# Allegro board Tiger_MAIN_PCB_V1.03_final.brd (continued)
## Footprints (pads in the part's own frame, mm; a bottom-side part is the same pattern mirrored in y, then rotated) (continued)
SMD-BATTERY-2900P-2N
  rect 3x4.2 smd: 1(14.5,0) 2(-14.5,0)
SMD-CN-50P-20N-H
  oval 0.28x1.25 smd: 1(-4.75,2.325) 2(-4.25,2.325) 3(-3.75,2.325) 4(-3.25,2.325) 5(-2.75,2.325) 6(-2.25,2.325) 7(-1.75,2.325) 8(-1.25,2.325) 9(-0.75,2.325) 10(-0.25,2.325) 11(0.25,2.325) 12(0.75,2.325) 13(1.25,2.325) 14(1.75,2.325) 15(2.25,2.325) 16(2.75,2.325) 17(3.25,2.325) 18(3.75,2.325) 19(4.25,2.325) 20(4.75,2.325)
  rect 2x3.4 smd: E1(-6.44,0.4) E2(6.44,0.4)
SMD-CN-100P-2N-V-CB
  rect 0.6x1.5 smd: 1(0.5,2.55) 2(-0.5,2.55)
  rect 1.2x1.8 smd: E1(-1.8,0) E2(1.8,0)
SMD-CN-100P-4N-V-CB
  rect 0.6x1.5 smd: 1(1.5,2.55) 2(0.5,2.55) 3(-0.5,2.55) 4(-1.5,2.55)
  rect 1.2x1.8 smd: E1(-2.8,0) E2(2.8,0)
SMD-CN-100P-6N-H
  rect 0.6x1.55 smd: 1(-2.5,3.875) 2(-1.5,3.875) 3(-0.5,3.875) 4(0.5,3.875) 5(1.5,3.875) 6(2.5,3.875)
  rect 1.2x2 smd: E1(-3.8,0) E2(3.8,0)
SMD-CN-100P-40AN-H
  rect 0.6x1.6 smd: 1(-9.5,-2.9) 2(-8.5,-2.9) 3(-7.5,-2.9) 4(-6.5,-2.9) 5(-5.5,-2.9) 6(-4.5,-2.9) 7(-3.5,-2.9) 8(-2.5,-2.9) 9(-1.5,-2.9) 10(-0.5,-2.9) 11(0.5,-2.9) 12(1.5,-2.9) 13(2.5,-2.9) 14(3.5,-2.9) 15(4.5,-2.9) 16(5.5,-2.9) 17(6.5,-2.9) 18(7.5,-2.9) 19(8.5,-2.9) 20(9.5,-2.9) 21(9.5,2.9) 22(8.5,2.9) 23(7.5,2.9) 24(6.5,2.9) 25(5.5,2.9) 26(4.5,2.9) 27(3.5,2.9) 28(2.5,2.9) 29(1.5,2.9) 30(0.5,2.9) 31(-0.5,2.9) 32(-1.5,2.9) 33(-2.5,2.9) 34(-3.5,2.9) 35(-4.5,2.9) 36(-5.5,2.9) 37(-6.5,2.9) 38(-7.5,2.9) 39(-8.5,2.9) 40(-9.5,2.9)
  rect 1.5x2.3 smd: E1(-11.5,-1.3) E2(11.5,-1.3)
SMD-CN-125P-2WBN
  rect 0.8x1.5 smd: 1(-0.625,2.49) 2(0.625,2.49)
  rect 2x2.5 smd: E1(-3.175,0) E2(3.175,0)
SMD-DDR4-50X820P-260N-AR
  round 1.1 hole 1.1 unplated: (-34.4,0)
  round 1.6 hole 1.6 unplated: (34.4,0)
  rect 0.28x2 smd: 1(33.375,4.1) 2(33.125,-4.1) 3(32.875,4.1) 4(32.625,-4.1) 5(32.375,4.1) 6(32.125,-4.1) 7(31.875,4.1) 8(31.625,-4.1) 9(31.375,4.1) 10(31.125,-4.1) 11(30.875,4.1) 12(30.625,-4.1) 13(30.375,4.1) 14(30.125,-4.1) 15(29.875,4.1) 16(29.625,-4.1) 17(29.375,4.1) 18(29.125,-4.1) 19(28.875,4.1) 20(28.625,-4.1) 21(28.375,4.1) 22(28.125,-4.1) 23(27.875,4.1) 24(27.625,-4.1) 25(27.375,4.1) 26(27.125,-4.1) 27(26.875,4.1) 28(26.625,-4.1) 29(26.375,4.1) 30(26.125,-4.1) 31(25.875,4.1) 32(25.625,-4.1) 33(25.375,4.1) 34(25.125,-4.1) 35(24.875,4.1) 36(24.625,-4.1) 37(24.375,4.1) 38(24.125,-4.1) 39(23.875,4.1) 40(23.625,-4.1) 41(23.375,4.1) 42(23.125,-4.1) 43(22.875,4.1) 44(22.625,-4.1) 45(22.375,4.1) 46(22.125,-4.1) 47(21.875,4.1) 48(21.625,-4.1) 49(21.375,4.1) 50(21.125,-4.1) 51(20.875,4.1) 52(20.625,-4.1) 53(20.375,4.1) 54(20.125,-4.1) 55(19.875,4.1) 56(19.625,-4.1) 57(19.375,4.1) 58(19.125,-4.1) 59(18.875,4.1) 60(18.625,-4.1) 61(18.375,4.1) 62(18.125,-4.1) 63(17.875,4.1) 64(17.625,-4.1) 65(17.375,4.1) 66(17.125,-4.1) 67(16.875,4.1) 68(16.625,-4.1) 69(16.375,4.1) 70(16.125,-4.1) 71(15.875,4.1) 72(15.625,-4.1) 73(15.375,4.1) 74(15.125,-4.1) 75(14.875,4.1) 76(14.625,-4.1) 77(14.375,4.1) 78(14.125,-4.1) 79(13.875,4.1) 80(13.625,-4.1) 81(13.375,4.1) 82(13.125,-4.1) 83(12.875,4.1) 84(12.625,-4.1) 85(12.375,4.1) 86(12.125,-4.1) 87(11.875,4.1) 88(11.625,-4.1) 89(11.375,4.1) 90(11.125,-4.1) 91(10.875,4.1) 92(10.625,-4.1) 93(10.375,4.1) 94(10.125,-4.1) 95(9.875,4.1) 96(9.625,-4.1) 97(9.375,4.1) 98(9.125,-4.1) 99(8.875,4.1) 100(8.625,-4.1) 101(8.375,4.1) 102(8.125,-4.1) 103(7.875,4.1) 104(7.625,-4.1) 105(7.375,4.1) 106(7.125,-4.1) 107(6.875,4.1) 108(6.625,-4.1) 109(6.375,4.1) 110(6.125,-4.1) 111(5.875,4.1) 112(5.625,-4.1) 113(5.375,4.1) 114(5.125,-4.1) 115(4.875,4.1) 116(4.625,-4.1) 117(4.375,4.1) 118(4.125,-4.1) 119(3.875,4.1) 120(3.625,-4.1) 121(3.375,4.1) 122(3.125,-4.1) 123(2.875,4.1) 124(2.625,-4.1) 125(2.375,4.1) 126(2.125,-4.1) 127(1.875,4.1) 128(1.625,-4.1) 129(1.375,4.1) 130(1.125,-4.1) 131(0.875,4.1) 132(0.625,-4.1) 133(0.375,4.1) 134(0.125,-4.1) 135(-0.125,4.1) 136(-0.375,-4.1) 137(-0.625,4.1) 138(-0.875,-4.1) 139(-1.125,4.1) 140(-1.375,-4.1) 141(-1.625,4.1) 142(-1.875,-4.1) 143(-2.125,4.1) 144(-2.375,-4.1) 145(-4.625,4.1) 146(-4.875,-4.1) 147(-5.125,4.1) 148(-5.375,-4.1) 149(-5.625,4.1) 150(-5.875,-4.1) 151(-6.125,4.1) 152(-6.375,-4.1) 153(-6.625,4.1) 154(-6.875,-4.1) 155(-7.125,4.1) 156(-7.375,-4.1) 157(-7.625,4.1) 158(-7.875,-4.1) 159(-8.125,4.1) 160(-8.375,-4.1) 161(-8.625,4.1) 162(-8.875,-4.1) 163(-9.125,4.1) 164(-9.375,-4.1) 165(-9.625,4.1) 166(-9.875,-4.1) 167(-10.125,4.1) 168(-10.375,-4.1) 169(-10.625,4.1) 170(-10.875,-4.1) 171(-11.125,4.1) 172(-11.375,-4.1) 173(-11.625,4.1) 174(-11.875,-4.1) 175(-12.125,4.1) 176(-12.375,-4.1) 177(-12.625,4.1) 178(-12.875,-4.1) 179(-13.125,4.1) 180(-13.375,-4.1) 181(-13.625,4.1) 182(-13.875,-4.1) 183(-14.125,4.1) 184(-14.375,-4.1) 185(-14.625,4.1) 186(-14.875,-4.1) 187(-15.125,4.1) 188(-15.375,-4.1) 189(-15.625,4.1) 190(-15.875,-4.1) 191(-16.125,4.1) 192(-16.375,-4.1) 193(-16.625,4.1) 194(-16.875,-4.1) 195(-17.125,4.1) 196(-17.375,-4.1) 197(-17.625,4.1) 198(-17.875,-4.1) 199(-18.125,4.1) 200(-18.375,-4.1) 201(-18.625,4.1) 202(-18.875,-4.1) 203(-19.125,4.1) 204(-19.375,-4.1) 205(-19.625,4.1) 206(-19.875,-4.1) 207(-20.125,4.1) 208(-20.375,-4.1) 209(-20.625,4.1) 210(-20.875,-4.1) 211(-21.125,4.1) 212(-21.375,-4.1) 213(-21.625,4.1) 214(-21.875,-4.1) 215(-22.125,4.1) 216(-22.375,-4.1) 217(-22.625,4.1) 218(-22.875,-4.1) 219(-23.125,4.1) 220(-23.375,-4.1) 221(-23.625,4.1) 222(-23.875,-4.1) 223(-24.125,4.1) 224(-24.375,-4.1) 225(-24.625,4.1) 226(-24.875,-4.1) 227(-25.125,4.1) 228(-25.375,-4.1) 229(-25.625,4.1) 230(-25.875,-4.1) 231(-26.125,4.1) 232(-26.375,-4.1) 233(-26.625,4.1) 234(-26.875,-4.1) 235(-27.125,4.1) 236(-27.375,-4.1) 237(-27.625,4.1) 238(-27.875,-4.1) 239(-28.125,4.1) 240(-28.375,-4.1) 241(-28.625,4.1) 242(-28.875,-4.1) 243(-29.125,4.1) 244(-29.375,-4.1) 245(-29.625,4.1) 246(-29.875,-4.1) 247(-30.125,4.1) 248(-30.375,-4.1) 249(-30.625,4.1) 250(-30.875,-4.1) 251(-31.125,4.1) 252(-31.375,-4.1) 253(-31.625,4.1) 254(-31.875,-4.1) 255(-32.125,4.1) 256(-32.375,-4.1) 257(-32.625,4.1) 258(-32.875,-4.1) 259(-33.125,4.1) 260(-33.375,-4.1)
  rect 3.6x4.6 smd: E1(-33.8,12) E2(33.8,12)
SMD-M2PCIE-50X750P-75AN
  round 0.254 hole 1.092 unplated: (-10,-1.499)
  round 0.254 hole 1.6 unplated: (10,-1.499)
  rect 0.305x1.575 smd: 1(-9.25,3.763) 2(-9,-3.763) 3(-8.75,3.763) 4(-8.5,-3.763) 5(-8.25,3.763) 6(-8,-3.763) 7(-7.75,3.763) 8(-7.5,-3.763) 9(-7.25,3.763) 10(-7,-3.763) 11(-6.75,3.763) 12(-6.5,-3.763) 13(-6.25,3.763) 14(-6,-3.763) 15(-5.75,3.763) 16(-5.5,-3.763) 17(-5.25,3.763) 18(-5,-3.763) 19(-4.75,3.763) 20(-4.5,-3.763) 21(-4.25,3.763) 22(-4,-3.763) 23(-3.75,3.763) 24(-3.5,-3.763) 25(-3.25,3.763) 26(-3,-3.763) 27(-2.75,3.763) 28(-2.5,-3.763) 29(-2.25,3.763) 30(-2,-3.763) 31(-1.75,3.763) 32(-1.5,-3.763) 33(-1.25,3.763) 34(-1,-3.763) 35(-0.75,3.763) 36(-0.5,-3.763) 37(-0.25,3.763) 38(0,-3.763) 39(0.25,3.763) 40(0.5,-3.763) 41(0.75,3.763) 42(1,-3.763) 43(1.25,3.763) 44(1.5,-3.763) 45(1.75,3.763) 46(2,-3.763) 47(2.25,3.763) 48(2.5,-3.763) 49(2.75,3.763) 50(3,-3.763) 51(3.25,3.763) 52(3.5,-3.763) 53(3.75,3.763) 54(4,-3.763) 55(4.25,3.763) 56(4.5,-3.763) 57(4.75,3.763) 58(5,-3.763) 59(5.25,3.763) 60(5.5,-3.763) 61(5.75,3.763) 62(6,-3.763) 63(6.25,3.763) 64(6.5,-3.763) 65(6.75,3.763) 66(7,-3.763) 67(7.25,3.763) 68(7.5,-3.763) 69(7.75,3.763) 70(8,-3.763) 71(8.25,3.763) 72(8.5,-3.763) 73(8.75,3.763) 74(9,-3.763) 75(9.25,3.763)
  rect 1.219x2.769 smd: E1(-10.39,3.001) E2(10.39,3.001)
SMD-M2PCIE-50X750P-75BN
  round 0.254 hole 1.092 unplated: (-10,-1.499)
  round 0.254 hole 1.6 unplated: (10,-1.499)
  rect 0.305x1.575 smd: 1(-9.25,3.763) 2(-9,-3.763) 3(-8.75,3.763) 4(-8.5,-3.763) 5(-8.25,3.763) 6(-8,-3.763) 7(-7.75,3.763) 8(-7.5,-3.763) 9(-7.25,3.763) 10(-7,-3.763) 11(-6.75,3.763) 12(-6.5,-3.763) 13(-6.25,3.763) 14(-6,-3.763) 15(-5.75,3.763) 16(-5.5,-3.763) 17(-5.25,3.763) 18(-5,-3.763) 19(-4.75,3.763) 20(-4.5,-3.763) 21(-4.25,3.763) 22(-4,-3.763) 23(-3.75,3.763) 24(-3.5,-3.763) 25(-3.25,3.763) 26(-3,-3.763) 27(-2.75,3.763) 28(-2.5,-3.763) 29(-2.25,3.763) 30(-2,-3.763) 31(-1.75,3.763) 32(-1.5,-3.763) 33(-1.25,3.763) 34(-1,-3.763) 35(-0.75,3.763) 36(-0.5,-3.763) 37(-0.25,3.763) 38(0,-3.763) 39(0.25,3.763) 40(0.5,-3.763) 41(0.75,3.763) 42(1,-3.763) 43(1.25,3.763) 44(1.5,-3.763) 45(1.75,3.763) 46(2,-3.763) 47(2.25,3.763) 48(2.5,-3.763) 49(2.75,3.763) 50(3,-3.763) 51(3.25,3.763) 52(3.5,-3.763) 53(3.75,3.763) 54(4,-3.763) 55(4.25,3.763) 56(4.5,-3.763) 57(4.75,3.763) 58(5,-3.763) 67(7.25,3.763) 68(7.5,-3.763) 69(7.75,3.763) 70(8,-3.763) 71(8.25,3.763) 72(8.5,-3.763) 73(8.75,3.763) 74(9,-3.763) 75(9.25,3.763)
  rect 1.219x2.769 smd: E1(-10.39,3.001) E2(10.39,3.001)
SMD-SATA-127P-22AN-L-KX
  round 1.4 hole 1.4 unplated: (-17,-1.35) (17,-1.35)
  oval 1.6x3.3 hole 1x2.6: E1(-18.71,1.05) E2(18.71,1.05)
  rect 0.9x2.6 smd: P1(-1.905,1.05) P2(-0.635,1.05) P3(0.635,1.05) P4(1.905,1.05) P5(3.175,1.05) P6(4.445,1.05) P7(5.715,1.05) P8(6.985,1.05) P9(8.255,1.05) P10(9.525,1.05) P11(10.795,1.05) P12(12.065,1.05) P13(13.335,1.05) P14(14.605,1.05) P15(15.875,1.05) S1(-15.875,1.05) S2(-14.605,1.05) S3(-13.335,1.05) S4(-12.065,1.05) S5(-10.795,1.05) S6(-9.525,1.05) S7(-8.255,1.05)
SMD-SD-250P-9N
  round 1 hole 1 unplated: (-11.45,6.5)
  round 1.5 hole 1.5 unplated: (9.53,6.5)
  rect 0.7x1.9 smd: 1(6.8,9.25) 2(4.3,9.25) 3(1.8,9.25) 4(-0.7,9.25) 5(-3.2,9.25) 6(-5.7,9.25) 7(-8.2,9.25) 8(-9.83,9.25) 9(9.3,9.25) 10(-12.37,9.25) 11(-11.08,9.25)
  rect 1.6x1.6 smd: E1(-14.05,7.55) E2(11.75,7.55) E3(-14.05,-6.65) E4(14.05,-6.65)
SMD-USB-100P-9AN
  rect 0.7x1.65 smd: 1(-3,1) 2(-1,1) 3(1,1) 4(3,1) 5(4,1) 6(2,1) 7(0,1) 8(-2,1) 9(-4,1)
  oval 1.6x3.4 hole 0.6x2.4: E1(-7.9,0) E2(7.9,0)
  rect 1.7x2.3 smd: E3(-7.68,-4.2) E4(7.68,-4.2)
SMY126X63
  rect 1.803x0.991 smd: 1(0,1.245) 2(0,-1.245)
SOD0806N
  rect 0.4x0.35 smd: N(-0.45,0) P(0.45,0)
SOD1713N
  rect 0.8x0.6 smd: N(1.25,0) P(-1.25,0)
SOD2514N
  rect 1.2x0.5 smd: N(-1.15,0) P(1.15,0)
SOD2818N
  rect 2.2x1.4 smd: N(1,0)
  rect 0.9x1.4 smd: P(-1.65,0)
SOD5225N
  rect 2x2 smd: N(-2.095,0) P(2.095,0)
SOD5336N
  rect 2.5x2.3 smd: N(2.15,0) P(-2.15,0)
SOIC127P540-8N
  rect 1.9x0.6 smd: 1(0,0) 2(0,-1.27) 3(0,-2.54) 4(0,-3.81) 5(6.756,-3.81) 6(6.756,-2.54) 7(6.756,-1.27) 8(6.756,0)
SOIC127P600-8N
  rect 1.9x0.6 smd: 1(-2.55,1.905) 2(-2.55,0.635) 3(-2.55,-0.635) 4(-2.55,-1.905) 5(2.55,-1.905) 6(2.55,-0.635) 7(2.55,0.635) 8(2.55,1.905)
SOIC127P605X520-8N
  rect 0.7x0.5 smd: 1(-2.825,1.905) 2(-2.825,0.635) 3(-2.825,-0.635) 4(-2.825,-1.905) 5(2.825,-1.905) 6(2.825,-0.635) 7(2.825,0.635)
  custom 1.12x1.12 smd: 8(0.7,0)
SOIC127P800-8N
  rect 1.8x0.6 smd: 1(-3.6,1.905) 2(-3.6,0.635) 3(-3.6,-0.635) 4(-3.6,-1.905) 5(3.6,-1.905) 6(3.6,-0.635) 7(3.6,0.635) 8(3.6,1.905)
SON50P200X200-8N
  oval 0.6x0.25 smd: 1(-1,0.749) 2(-1,0.249) 3(-1,-0.251) 4(-1,-0.751) 5(1,-0.751) 6(1,-0.251) 7(1,0.249) 8(1,0.749)
  rect 0.9x1.6 smd: E1(0,0)
SON65P330X330-8N
  rect 0.65x0.35 smd: 1(-1.65,0.975) 2(-1.65,0.325) 3(-1.65,-0.325) 4(-1.65,-0.975) 5(1.65,-0.975) 6(1.65,-0.325) 7(1.65,0.325)
  custom 0.65x0.65 smd: 8(0,0)
SOP35P100-3N
  rect 0.3x0.3 smd: 1(-0.35,-0.425) 2(0.35,-0.425) 3(0,0.425)
SOP99P996-24N
  rect 1.5x0.72 smd: 1(-4.5,5.484) 2(-4.5,4.494) 3(-4.5,3.504) 4(-4.5,2.514) 5(-4.5,1.524) 6(-4.5,0.534) 7(-4.5,-0.456) 8(-4.5,-1.446) 9(-4.5,-2.436) 10(-4.5,-3.426) 11(-4.5,-4.416) 12(-4.5,-5.406) 13(4.5,-5.406) 14(4.5,-4.416) 15(4.5,-3.426) 16(4.5,-2.436) 17(4.5,-1.446) 18(4.5,-0.456) 19(4.5,0.534) 20(4.5,1.524) 21(4.5,2.514) 22(4.5,3.504) 23(4.5,4.494) 24(4.5,5.484)
SOP127P600-9N
  rect 1.9x0.6 smd: 1(-2.55,1.905) 2(-2.55,0.635) 3(-2.55,-0.635) 4(-2.55,-1.905) 5(2.55,-1.905) 6(2.55,-0.635) 7(2.55,0.635) 8(2.55,1.905)
  rect 2.6x3 smd: E1(0,0)
SOT65P190-5N
  oval 1.1x0.35 smd: 1(-0.95,0.65) 2(-0.95,0) 3(-0.95,-0.65) 4(0.95,-0.65) 5(0.95,0.65)
SOT65P210-3N
  rect 1.2x0.45 smd: 1(-0.9,0.65) 2(-0.9,-0.65) 3(0.9,0)
SOT65P210-5N
  rect 1.1x0.4 smd: 1(-0.95,0.65) 2(-0.95,0) 3(-0.95,-0.65) 4(0.95,-0.65) 5(0.95,0.65)
SOT95P230-3N
  rect 1.25x0.6 smd: 1(-1.05,0.95) 2(-1.05,-0.95) 3(1.05,0)
SOT95P240-3N
  rect 1.4x0.6 smd: 1(-1,0.95) 2(-1,-0.95) 3(1,0)
SOT95P280-3N
  rect 1.35x0.6 smd: 1(-1.25,0.95) 2(-1.25,-0.95) 3(1.25,0)
SOT95P280-5N
  rect 1.3x0.6 smd: 1(-1.25,0.95) 2(-1.25,0) 3(-1.25,-0.95) 4(1.25,-0.95) 5(1.25,0.95)
SOT229P990-3N
  rect 1x2.2 smd: 1(-2.29,-3.35) 2(2.29,-3.35)
  rect 5.5x5.3 smd: 3(0,3.15)
TDFN50P300X300-10N
  oval 0.65x0.25 smd: 1(-1.325,1) 2(-1.325,0.5) 3(-1.325,0) 4(-1.325,-0.5) 5(-1.325,-1) 6(1.325,-1) 7(1.325,-0.5) 8(1.325,0) 9(1.325,0.5) 10(1.325,1)
  rect 1.5x2.5 smd: E1(0,0)
TEST60
  round 0.6 smd: 1(0,0)
TEST100
  round 1 smd: 1(0,0)
TH-CN-200P-2N-H
  round 1.4 hole 0.8: 1(-1,0) 2(1,0)
TH-DCIN-540P-3N
  round 1.3 hole 1.3 unplated: (-4.25,4.5) (4.25,-4.5)
  oval 2x3.5 hole 0.9x2.5: B(-4,1)
  oval 3.5x2 hole 2.5x0.9: C(-2,-4.4) D(2.6,-2)
TH-EARPHONE-330X400P-5N
  round 1.1 hole 1.1 unplated: (0,-2.55)
  oval 2.1x1.2 hole 1.5x0.6: 2(0,2.55)
  oval 1.2x2.1 hole 0.6x1.5: 3(-4,1.65) 4(4,1.65) 5(-2.5,-1.65) 6(2.5,-1.65)
TH-RJ45-127P-8N
  round 3.2 hole 3.2 unplated: (-5.715,1.1) (5.715,1.1)
  round 1.05 hole 0.7: 1(-4.445,7.45) 2(-3.175,7.45) 3(-1.905,7.45) 4(-0.635,7.45) 5(0.635,7.45) 6(1.905,7.45) 7(3.175,7.45) 8(4.445,7.45)
  round 2.6 hole 1.6: E1(-7.875,4.99) E2(7.875,4.99)
TH-SW-420P-2N
  round 1 hole 1 unplated: (-1.15,0) (1.15,0)
  rect 1.2x1.5 smd: 1(-2.1,1) 2(2.1,1)
  rect 1.3x1.2 smd: E1(-3.525,-0.8) E2(3.525,-0.8)
TH-USB-250PX200P-4BN
  round 1.55 hole 0.95: 1(-3.5,0.81) 2(-1,0.81) 3(1,0.81) 4(3.5,0.81)
  oval 1.2x2.1 hole 0.6x1.5: E1(-6.4,0.21) E2(6.4,0.21)
THR-CPR50-630X1100N
  round 1.5 hole 0.7: 1(-1.25,0) 2(1.25,0)
TQFN40P500X500-40N
  oval 0.8x0.2 smd: 1(-2.55,1.8) 2(-2.55,1.4) 3(-2.55,1) 4(-2.55,0.6) 5(-2.55,0.2) 6(-2.55,-0.2) 7(-2.55,-0.6) 8(-2.55,-1) 9(-2.55,-1.4) 10(-2.55,-1.8) 21(2.55,-1.8) 22(2.55,-1.4) 23(2.55,-1) 24(2.55,-0.6) 25(2.55,-0.2) 26(2.55,0.2) 27(2.55,0.6) 28(2.55,1) 29(2.55,1.4) 30(2.55,1.8)
  oval 0.2x0.8 smd: 11(-1.8,-2.55) 12(-1.4,-2.55) 13(-1,-2.55) 14(-0.6,-2.55) 15(-0.2,-2.55) 16(0.2,-2.55) 17(0.6,-2.55) 18(1,-2.55) 19(1.4,-2.55) 20(1.8,-2.55) 31(1.8,2.55) 32(1.4,2.55) 33(1,2.55) 34(0.6,2.55) 35(0.2,2.55) 36(-0.2,2.55) 37(-0.6,2.55) 38(-1,2.55) 39(-1.4,2.55) 40(-1.8,2.55)
  rect 3.6x3.6 smd: E1(0,0)
TSOP65P490-8N
  rect 1.45x0.4 smd: 1(-2.2,0.975) 2(-2.2,0.325) 3(-2.2,-0.325) 4(-2.2,-0.975) 5(2.2,-0.975) 6(2.2,-0.325) 7(2.2,0.325) 8(2.2,0.975)
TSSOP65P640-16AN
  rect 1.6x0.35 smd: 1(-3,2.275) 2(-3,1.625) 3(-3,0.975) 4(-3,0.325) 5(-3,-0.325) 6(-3,-0.975) 7(-3,-1.625) 8(-3,-2.275) 9(3,-2.275) 10(3,-1.625) 11(3,-0.975) 12(3,-0.325) 13(3,0.325) 14(3,0.975) 15(3,1.625) 16(3,2.275)
  rect 3x2.8 smd: E1(0,0)
unnamed
  round 2 hole 2 unplated: (0,0)

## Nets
+V1.05A_EN: C804.1 R462.2 R769.1 U41.1(EN_PSV)
+V1.5S: C431.2 C565.1 C566.1 FB10.2 R361.2 R534.2 R819.2 R826.2 U35.3(VOUT1) U35.4(VOUT2)
+V1.8U_2.5U_MEM: C283.1 C284.1 C513.1 C523.1 C678.1 C679.2 C680.2 CN1.257(VPP1) CN1.259(VPP2) R464.2 U21.3(VOUT1) U21.4(VOUT2)
+V1P00A: C220.2 C224.2 C227.1 C230.2 C232.2 C234.1 C237.1 C238.1 C239.2 C240.2 C241.2 C242.1 C243.1 C685.2 C686.2 C759.1 CP13.1 L12.2 R4.1 R719.1 R764.2 R816.2 U1.A10(VCC24TBT_1P0_A10) U1.A14(VCC19P2_1P0_A14) U1.AB17(VCCDUSB_1P0_AB17) U1.AB19(VCCPRIM_1P0_AB19) U1.AB20(VCCPRIM_1P0_AB20) U1.AF18(VCCPRIM_CORE_AF18) U1.AF19(VCCPRIM_CORE_AF19) U1.AF20(VCCSRAM_1P0_AF20) U1.AF21(VCCSRAM_1P0_AF21) U1.AK20(VCCFHV_2P8_AK20) U1.K15(VCCAMPHYPLL_1P0_K15) U1.K17(VCCMPHYAON_1P0_K17) U1.K19(VCCF100_1P0_K19) U1.L1(VCCMPHYAON_1P0_L1) U1.L15(VCCAMPHYPLL_1P0_L15) U1.L19(VCCF24NS_1P0_L19) U1.L21(VCCF135_1P0_L21) U1.N15(VCCMPHYGTAON_1P0_N15) U1.N16(VCCMPHYGTAON_1P0_N16) U1.N17(VCCMPHYGTAON_1P0_N17) U1.N18(VCCAPLLEBB_1P0_N18) U1.N20(VCCF100OC_1P0_N20) U1.P15(VCCMPHYGTAON_1P0_P15) U1.P16(VCCMPHYGTAON_1P0_P16) U1.P18(VCCPRIM_1P0_P18) U1.T1(VCCDTS_1P0_T1) U1.T19(VCCSRAM_1P0_T19) U1.T20(VCCSRAM_1P0_T20) U1.V15(VCCAPLL_1P0_V15) U1.V20(VCCPRIM_CORE_V20) U1.V21(VCCPRIM_CORE_V21) U1.Y18(VCCDUSB_1P0_Y18) U41.3(VOUT) U56.1(VIN1) U56.2(VIN2) U67.1(VIN1) U67.2(VIN2)
+V1P00A_FB: R764.1 R766.2 U41.5(VFB)
+V1P00S_VCCST: C208.2 C218.2 C219.2 C687.2 R20.1 R28.1 R29.1 R124.1 R125.1 R713.2 R714.1 R716.2 U1.A18(VCCST) U1.K20(VCCSFR_K20) U1.K21(VCCSFR_K21) U56.7(VOUT2) U56.8(VOUT1)
+V1P00S_VCCSTG: C176.1 C177.1 C178.1 C179.1 C180.1 C181.1 C182.1 C183.2 C184.2 C190.1 C216.2 C690.2 R27.1 R30.2 R31.2 R32.2 R33.2 R34.2 R35.2 R59.2 R123.2 U1.A22(VCCSTG) U1.AK28(VCCIO_AK28) U1.AK30(VCCIO_AK30) U1.AL30(VCCIO_AL30) U1.AL42(VCCIO_AL42) U1.AM28(VCCIO_AM28) U1.AM30(VCCIO_AM30) U1.AM42(VCCIO_AM42) U67.7(VOUT2) U67.8(VOUT1)
+V1P8A: C339.1 C340.1 C701.2 L25.2 R121.2 R128.2 R771.2 R801.2 U59.1(VIN1) U59.2(VIN2)
+V1P8A_SIP: C231.2 R120.2 R126.2 R128.1 U1.AA1(VCCATS_AA1) U1.AF16(VCCPGPPF_AF16)
+V1P8S: C709.2 FB12.2 R98.1 R99.1 R106.1 R107.1 R831.2 U59.7(VOUT2) U59.8(VOUT1)
+V3.3_LAN: C375.1 C377.1 C378.1 C379.1 C380.1 C381.1 C382.1 C383.2 C384.1 R311.1 R321.2 R325.1 R326.1 R328.1 U8.1(VOUT) U9.12(AVDD33(NC)) U9.27(DVDD33) U9.34(VDDREG) U9.35(VDDREGA) U9.39(DVDD3) U9.42(AVDD33) U9.47(AVDD33A) U9.48(AVDD33B) U10.5(VCC)
+V3.3_WIFI: C463.1 C2775.2 C2776.2 C2777.2 C2778.1 C2779.2 C2780.2 CN26.2(3.3V_2) CN26.4(3.3V_4) CN26.72(3.3V_72) CN26.74(3.3V_74) FB15.1 U18.5(VCC) U19.1(VOUT)
+V3.3A_KBC: C477.2 C479.2 C486.1 FB16.1 R379.1 R380.1 R381.1 R383.2 R384.1 R387.1 R388.1 R393.1 R405.1 R406.2 R407.1 R408.2 R420.1 R422.1 R427.2 R428.2 R506.2 U22.26(VSTBY1) U22.50(VSTBY2) U22.92(VSTBY3) U22.114(VSTBY4) U22.121(VSTBY6) U22.127(VSTBY5) U24.8(VCC)
+V3.3AVCC: C480.1 FB16.2 U22.74(AVCC)
+V3.3S: C248.2 C249.2 C429.2 C430.1 C459.2 C485.2 C510.2 C792.1 C794.2 CN1.255(VDDSPD) CN16.1 CN16.2 CN16.14 CN16.15 CN16.18 FB2.2 FB9.2 FB11.2 FB19.2 FB37.1 FB39.2 Q2.1(G) Q3.1(G) Q43.1(S1) Q43.2(S2) Q43.3(S3) R15.1 R16.1 R69.1 R84.2 R85.2 R95.1 R97.2 R108.1 R109.1 R110.1 R111.1 R180.1 R199.1 R247.2 R264.2 R271.1 R315.2 R369.1 R370.1 R371.1 R382.2 R386.2 R389.2 R398.2 R491.2 R537.1 R607.1 R818.2 R3107.1 R3108.1 U2.5(VCC) U17.5(VCC) U23.5(VCC) U27.5(VCC)
+V3.3S_AUDIO: C434.2 C435.2 FB9.1 FB13.1 R346.1 R360.2 U16.36(CPVDD)
+V3.3S_MSATA: C285.2 C286.1 C287.2 C292.2 CN5.2(3.3V_2) CN5.4(3.3V_4) CN5.12(3.3V_12) CN5.14(3.3V_14) CN5.16(3.3V_16) CN5.18(3.3V_18) CN5.70(3.3V_70) CN5.72(3.3V_72) CN5.74(3.3V_74) FB2.1 FB3.1
+V3P3_BIOS_SPI: C746.2 C747.2 D1.N R707.1 R708.1 R709.1 U42.8(VCC)
+V3P3A: C282.1 C373.1 C376.1 C464.2 C469.1 C708.2 C797.1 C803.1 D1.P FB15.2 LED2.1(P) Q43.5(D1) Q43.6(D2) Q43.7(D3) Q43.8(D4) Q68.1(S1) Q68.2(S2) Q68.3(S3) R1.1 R2.1 R14.1 R21.1 R37.1 R38.1 R55.2 R56.2 R57.1 R58.1 R61.1 R62.1 R63.1 R64.1 R65.1 R68.1 R75.1 R77.1 R82.1 R83.1 R86.1 R87.2 R90.2 R92.1 R93.2 R94.1 R105.2 R112.2 R113.1 R114.1 R115.1 R129.2 R131.2 R134.1 R140.2 R253.1 R306.2 R377.2 R468.2 R523.1 R524.2 R544.2 R613.2 R632.1 R663.2 R732.2 R733.2 R767.2 R769.2 U5.1(VDD) U6.5(VCC) U8.5(VIN) U19.5(VIN)
+V3P3A_DSW: C706.1 C768.1 C771.1 CP14.1 D30.P FB44.1 FB45.2 L4.2 Q68.5(D1) Q68.6(D2) Q68.7(D3) Q68.8(D4) R9.1 R10.1 R11.1 R18.1 R19.1 R23.1 R54.1 R71.1 R72.1 R132.2 R383.1 R613.1 R774.1 R776.2 R829.1
+V3P3A_RTC: C233.2 D30.N D31.N R6.2 R7.2 R12.2 U1.AK19(VCCPRTC_3P3_AK19) U1.BB14(VCCPRTC_3P3_BB14)
+V3P3A_SIP: C221.2 C222.2 C223.2 C225.2 C226.2 C229.2 C245.2 R119.2 R127.2 R129.1 R133.2 U1.AG15(VCCPGPPB_AG15) U1.AJ16(VCCPSPI_AJ16) U1.AJ21(VCCPFUSE_3P3_AJ21) U1.AK15(VCCPGPPA_AK15) U1.AK17(VCCPRTCPRIM_3P3_AK17) U1.T16(VCCPGPPE_T16) U1.V19(VCCPHVC_3P3) U1.Y16(VCCPGPPC_Y16)
+V5_AVDD: C439.2 C440.1 FB8.1 U16.26(AVDD1)
+V5_PVDD: C447.2 C448.1 C449.2 C450.1 FB7.1 U16.41(PVDD1) U16.46(PVDD2)
+V5A: C321.1 C323.1 C325.1 C405.2 C406.2 C512.1 C689.2 C696.2 C702.2 C705.1 C711.1 C714.1 C716.2 C758.2 C772.1 C777.1 C778.1 C791.2 C807.2 CP15.1 D24.1(X1) D26.P F2.1 F3.1 F4.1 F5.1 L26.1 Q60.5(D1) Q60.6(D2) Q60.7(D3) Q60.8(D4) R270.2 R553.1 R558.1 R561.1 R563.1 R763.2 R782.1 R800.2 R813.2 R814.2 U12.5(VIN) U21.6(VCNTL) U29.9(VCC) U38.5(VIN) U39.5(VIN) U40.5(VIN) U41.10(V5DRV) U45.6(VCC) U50.6(VCC) U54.6(VCC) U56.4(VBIAS) U59.4(VBIAS) U67.4(VBIAS) U71.14(VO1) U103.9(ISEN1_B) U103.10(ISEN2_B) U103.34(VCC)
+V5S: C424.2 C425.1 C426.2 C427.1 C564.1 C793.2 C796.2 FB3.2 FB7.2 FB8.2 FB21.2 FB40.2 Q60.1(S1) Q60.2(S2) Q60.3(S3) R152.1 R246.2 R342.1 R399.1 R400.1 R404.1 R535.2 R608.1 R625.2 R817.2 U35.6(VCNTL)
+V5S_HDD: C2836.1 C2837.2 C2838.2 C2839.1 CN3.P8 CN3.P9 FB40.1 R748.1
+V15A: C776.1 D25.2(X2) R70.1 R806.1 R809.1
+VCCCORE: C15.1 C16.1 C17.1 C18.1 C19.1 C20.1 C21.1 C22.1 C23.1 C24.1 C25.1 C26.1 C27.1 C28.1 C29.1 C30.1 C31.1 C32.2 C33.2 C34.2 C35.2 C36.2 C37.2 C38.2 C39.2 C40.2 C41.2 C42.2 C43.2 C44.2 C45.2 C46.2 C47.1 C48.1 C49.1 C50.1 C51.1 C52.1 C53.1 C54.1 C55.1 C56.1 C57.1 C58.1 C59.1 C60.1 C61.1 C62.1 C63.1 C64.1 C65.1 C66.1 C67.1 C68.1 C69.1 C70.1 C71.1 C72.1 C73.1 C74.1 C75.1 C76.1 C77.1 C78.1 C79.1 C80.1 C81.1 C303.2 C304.1 C307.1 CP1.1 CP2.1 LPM1.2 R214.2 R215.1 R217.1 R244.1 R681.2 R815.2 U1.A30(VCCCORE_A30) U1.A34(VCCCORE_A34) U1.A39(VCCCORE_A39) U1.A44(VCCCORE_A44) U1.AK33(VCCCORE_AK33) U1.AK35(VCCCORE_AK35) U1.AK37(VCCCORE_AK37) U1.AK38(VCCCORE_AK38) U1.AK40(VCCCORE_AK40) U1.AL33(VCCCORE_AL33) U1.AL37(VCCCORE_AL37) U1.AL40(VCCCORE_AL40) U1.AM32(VCCCORE_AM32) U1.AM33(VCCCORE_AM33) U1.AM35(VCCCORE_AM35) U1.AM37(VCCCORE_AM37) U1.AM38(VCCCORE_AM38) U1.G30(VCCCORE_G30) U1.G32(VCCCORE_G32) U1.G33(VCCCORE_G33) U1.G35(VCCCORE_G35) U1.G37(VCCCORE_G37) U1.G38(VCCCORE_G38) U1.G40(VCCCORE_G40) U1.G42(VCCCORE_G42) U1.J30(VCCCORE_J30) U1.J33(VCCCORE_J33) U1.J37(VCCCORE_J37) U1.J40(VCCCORE_J40) U1.K33(VCCCORE_K33) U1.K35(VCCCORE_K35) U1.K37(VCCCORE_K37) U1.K38(VCCCORE_K38) U1.K40(VCCCORE_K40) U1.K42(VCCCORE_K42) U1.K43(VCCCORE_K43)
+VCCDSW_1P0: C228.1 U1.AL1(VCCDSW_1P0_AL1)
+VCCGT: C82.1 C83.1 C84.1 C85.1 C86.1 C87.1 C88.1 C89.1 C90.1 C91.1 C92.1 C93.1 C94.2 C95.2 C96.2 C97.2 C98.2 C99.2 C100.2 C101.2 C102.2 C103.2 C104.2 C105.2 C106.1 C107.1 C108.1 C109.1 C110.1 C111.1 C112.1 C113.1 C114.1 C115.1 C116.1 C117.1 C118.1 C119.1 C120.2 C121.2 C122.2 C123.2 C124.2 C125.2 C126.2 C127.2 C128.2 C129.2 C130.2 C131.2 C132.2 C133.2 C134.2 C135.2 C136.2 C137.2 C138.2 C139.2 C140.2 C141.2 C142.2 C143.2 C144.2 C145.2 C146.2 C147.2 C148.2 C149.2 C150.1 C151.1 C152.1 C153.1 C154.1 C155.1 C156.1 C157.1 C158.1 C159.1 C160.1 C161.1 C162.1 C163.1 C164.1 C165.1 C166.1 C167.1 C168.1 C169.1 C294.1 C296.1 C297.1 CP3.1 CP4.1 CP18.1 LPM8.1 R204.2 R206.1 R207.2 R212.2 R591.2 U1.A48(VCCGT_A48) U1.A53(VCCGT_A53) U1.A58(VCCGT_A58) U1.A62(VCCGT_A62) U1.A66(VCCGT_A66) U1.AA63(VCCGT_AA63) U1.AA64(VCCGT_AA64) U1.AA66(VCCGT_AA66) U1.AA67(VCCGT_AA67) U1.AA69(VCCGT_AA69) U1.AA70(VCCGT_AA70) U1.AA71(VCCGT_AA71) U1.AC64(VCCGT_AC64) U1.AC65(VCCGT_AC65) U1.AC66(VCCGT_AC66) U1.AC67(VCCGT_AC67) U1.AC68(VCCGT_AC68) U1.AC69(VCCGT_AC69) U1.AC70(VCCGT_AC70) U1.AC71(VCCGT_AC71) U1.J43(VCCGT_J43) U1.J45(VCCGT_J45) U1.J46(VCCGT_J46) U1.J48(VCCGT_J48) U1.J50(VCCGT_J50) U1.J52(VCCGT_J52) U1.J53(VCCGT_J53) U1.J55(VCCGT_J55) U1.J56(VCCGT_J56) U1.J58(VCCGT_J58) U1.J60(VCCGT_J60) U1.K48(VCCGT_K48) U1.K50(VCCGT_K50) U1.K52(VCCGT_K52) U1.K53(VCCGT_K53) U1.K55(VCCGT_K55) U1.K56(VCCGT_K56) U1.K58(VCCGT_K58) U1.K60(VCCGT_K60) U1.L62(VCCGT_L62) U1.L63(VCCGT_L63) U1.L64(VCCGT_L64) U1.L65(VCCGT_L65) U1.L66(VCCGT_L66) U1.L67(VCCGT_L67) U1.L68(VCCGT_L68) U1.L69(VCCGT_L69) U1.L70(VCCGT_L70) U1.L71(VCCGT_L71) U1.M62(VCCGT_M62) U1.N63(VCCGT_N63) U1.N64(VCCGT_N64) U1.N66(VCCGT_N66) U1.N67(VCCGT_N67) U1.N69(VCCGT_N69) U1.N70(VCCGT_N70) U1.N71(VCCGT_N71) U1.R63(VCCGT_R63) U1.R64(VCCGT_R64) U1.R65(VCCGT_R65) U1.R66(VCCGT_R66) U1.R67(VCCGT_R67) U1.R68(VCCGT_R68) U1.R69(VCCGT_R69) U1.R70(VCCGT_R70) U1.R71(VCCGT_R71) U1.T62(VCCGT_T62) U1.U65(VCCGT_U65) U1.U68(VCCGT_U68) U1.U71(VCCGT_U71) U1.W63(VCCGT_W63) U1.W64(VCCGT_W64) U1.W65(VCCGT_W65) U1.W66(VCCGT_W66) U1.W67(VCCGT_W67) U1.W68(VCCGT_W68) U1.W69(VCCGT_W69) U1.W70(VCCGT_W70) U1.W71(VCCGT_W71) U1.Y62(VCCGT_Y62)
+VCCPAZIO: C244.2 R126.1 R127.1 R796.1 R799.1 R826.1 U1.AJ19(VCCPAZIO_AJ19)
+VCCPDSW_3P3: C235.1 C236.1 R132.1 R133.1 U1.AD17(VCCPDSW_3P3_AD17) U1.AD18(VCCPDSW_3P3_AD18) U1.AJ17(VCCPDSW_3P3_AJ17)
+VCCPGPPD: R119.1 R120.1 U1.Y15(VCCPGPPD_Y15)
+VCCPGPPG: R121.1 R131.1 U1.AD15(VCCPGPPG_AD15)
+VCCSA: C193.2 C194.2 C195.2 C196.2 C197.2 C198.2 C199.1 C202.2 C203.2 C204.2 C205.2 C206.2 C207.2 C209.1 C210.1 C211.1 C212.1 C213.1 C214.1 C215.1 C310.1 C311.2 C315.2 C2852.1 CP8.1 LPM10.1 R223.2 R225.1 R228.1 R237.2 R672.2 U1.AK23(VCCSA_AK23) U1.AK25(VCCSA_AK25) U1.G23(VCCSA_G23) U1.G25(VCCSA_G25) U1.G27(VCCSA_G27) U1.G28(VCCSA_G28) U1.J22(VCCSA_J22) U1.J23(VCCSA_J23) U1.J27(VCCSA_J27) U1.K23(VCCSA_K23) U1.K25(VCCSA_K25) U1.K27(VCCSA_K27) U1.K28(VCCSA_K28) U1.K30(VCCSA_K30)
+VDDQ_MEM: C170.2 C171.2 C172.2 C173.2 C174.2 C175.2 C185.1 C186.1 C187.1 C188.1 C189.1 C191.1 C192.1 C200.1 C201.2 C217.2 C334.1 C640.2 C641.2 C642.2 C643.2 C644.2 C645.2 C646.2 C650.2 C651.2 C652.2 C653.2 C654.2 C655.2 C656.2 C657.2 C658.2 C698.2 CN1.12(DM0*/DBI0*) CN1.33(DM1*/DBI1*) CN1.54(DM2*/DBI2*) CN1.75(DM3*/DBI3*) CN1.96(DM8*/DBI8*) CN1.111(VDD1) CN1.112(VDD2) CN1.117(VDD3) CN1.118(VDD4) CN1.123(VDD5) CN1.124(VDD6) CN1.129(VDD7) CN1.130(VDD8) CN1.135(VDD9) CN1.136(VDD10) CN1.141(VDD11) CN1.142(VDD12) CN1.147(VDD13) CN1.148(VDD14) CN1.153(VDD15) CN1.154(VDD16) CN1.159(VDD17) CN1.160(VDD18) CN1.163(VDD19) CN1.178(DM4*/DBI4*) CN1.199(DM5*/DBI5*) CN1.220(DM6*/DBI6*) CN1.241(DM7*/DBI7*) CP7.1 CP9.1 L5.2 R45.2 R385.1 R471.2 R472.2 R490.1 R492.1 R493.1 R494.1 R495.1 R496.1 R497.1 R498.2 R501.1 R546.2 R811.2 U1.AL23(VCCSFR_OC) U1.AM40(VCCDDQ_CLK) U1.AU23(VCCDU_AU23) U1.AU28(VCCDU_AU28) U1.AU35(VCCDU_AU35) U1.AU42(VCCDU_AU42) U1.BB23(VCCDU_BB23) U1.BB32(VCCDU_BB32) U1.BB41(VCCDU_BB41) U1.BB47(VCCDU_BB47) U1.BB51(VCCDU_BB51) U4.5(VCC) U29.2(VDDQSNS) U29.28(LDOIN)
+VDDQ_VTT: C328.1 C659.2 C662.2 C663.2 C664.2 C665.2 C699.1 CN1.258(VTT) R820.2 U29.29(VTT) U29.31(VTTSNS)
AGND: B1.2(S) C413.2 C414.2 C418.2 C419.2 C421.2 C422.2 C428.2 C432.1 C439.1 C440.2 C441.1 C442.2 C444.1 CN42.1 CN42.E1 CN42.E2 FB14.2 J2.2 J2.5 J3.2 J3.5 Q36.2(S) R357.2 R363.2 R364.2 U16.25(AVSS1) U16.38(AVSS2)
AVDD2_AUDIO: C441.2 C442.1 FB10.1 FB11.1 FB12.1 U16.40(AVDD2)
AVDD33: C2788.2 C2789.1 FB20.1 U95.4(AVDD33)
GND: C1.2 C2.2 C3.2 C4.2 C5.2 C6.2 C13.1 C14.2 C15.2 C16.2 C17.2 C18.2 C19.2 C20.2 C21.2 C22.2 C23.2 C24.2 C25.2 C26.2 C27.2 C28.2 C29.2 C30.2 C31.2 C32.1 C33.1 C34.1 C35.1 C36.1 C37.1 C38.1 C39.1 C40.1 C41.1 C42.1 C43.1 C44.1 C45.1 C46.1 C47.2 C48.2 C49.2 C50.2 C51.2 C52.2 C53.2 C54.2 C55.2 C56.2 C57.2 C58.2 C59.2 C60.2 C61.2 C62.2 C63.2 C64.2 C65.2 C66.2 C67.2 C68.2 C69.2 C70.2 C71.2 C72.2 C73.2 C74.2 C75.2 C76.2 C77.2 C78.2 C79.2 C80.2 C81.2 C82.2 C83.2 C84.2 C85.2 C86.2 C87.2 C88.2 C89.2 C90.2 C91.2 C92.2 C93.2 C94.1 C95.1 C96.1 C97.1 C98.1 C99.1 C100.1 C101.1 C102.1 C103.1 C104.1 C105.1 C106.2 C107.2 C108.2 C109.2 C110.2 C111.2 C112.2 C113.2 C114.2 C115.2 C116.2 C117.2 C118.2 C119.2 C120.1 C121.1 C122.1 C123.1 C124.1 C125.1 C126.1 C127.1 C128.1 C129.1 C130.1 C131.1 C132.1 C133.1 C134.1 C135.1 C136.1 C137.1 C138.1 C139.1 C140.1 C141.1 C142.1 C143.1 C144.1 C145.1 C146.1 C147.1 C148.1 C149.1 C150.2 C151.2 C152.2 C153.2 C154.2 C155.2 C156.2 C157.2 C158.2 C159.2 C160.2 C161.2 C162.2 C163.2 C164.2 C165.2 C166.2 C167.2 C168.2 C169.2 C170.1 C171.1 C172.1 C173.1 C174.1 C175.1 C176.2 C177.2 C178.2 C179.2 C180.2 C181.2 C182.2 C183.1 C184.1 C185.2 C186.2 C187.2 C188.2 C189.2 C190.2 C191.2 C192.2 C193.1 C194.1 C195.1 C196.1 C197.1 C198.1 C199.2 C200.2 C201.1 C202.1 C203.1 C204.1 C205.1 C206.1 C207.1 C208.1 C209.2 C210.2 C211.2 C212.2 C213.2 C214.2 C215.2 C216.1 C217.1 C218.1 C219.1 C220.1 C221.1 C222.1 C223.1 C224.1 C225.1 C226.1 C227.2 C228.2 C229.1 C230.1 C231.1 C232.1 C233.1 C234.2 C235.2 C236.2 C237.2 C238.2 C239.1 C240.1 C241.1 C242.2 C243.2 C244.1 C245.1 C248.1 C249.1 C250.1 C264.2 C282.2 C283.2 C284.2 C285.1 C286.2 C287.1 C292.1 C293.2 C296.2 C298.2 C300.1 C301.1 C302.1 C304.2 C305.1 C306.1 C308.1 C309.2 C310.2 C312.2 C313.2 C314.2 C315.1 C316.2 C317.1 C319.2 C320.1 C321.2 C323.2 C324.1 C325.2 C328.2 C329.2 C334.2 C339.2 C340.2 C341.2 C343.2 C368.1 C369.1 C371.2 C372.2 C373.2 C374.1 C375.2 C376.2 C377.2 C378.2 C379.2 C380.2 C381.2 C382.2 C383.1 C384.2 C385.1 C386.2 C387.2 C388.2 C389.2 C390.2 C391.2 C392.2 C393.2 C396.1 C397.2 C398.1 C403.2 C404.2 C405.1 C406.1 C407.1 C408.1 C409.2 C410.2 C416.1 C417.1 C424.1 C425.2 C426.1 C427.2 C429.1 C430.2 C431.1 C433.2 C434.1 C435.1 C436.2 C447.1 C448.2 C449.1 C450.2 C451.2 C452.1 C453.1 C454.1 C455.1 C456.1 C457.1 C458.1 C459.1 C461.1 C463.2 C464.1 C469.2 C470.1 C477.1 C479.1 C480.2 C481.1 C482.2 C483.2 C484.2 C485.1 C486.2 C487.2 C488.2 C489.2 C490.1 C491.2 C495.1 C510.1 C511.2 C512.2 C513.2 C523.2 C535.2 C563.2 C564.2 C565.2 C566.2 C603.2 C607.1 C608.1 C609.1 C610.2 C633.2 C634.2 C635.2 C640.1 C641.1 C642.1 C643.1 C644.1 C645.1 C646.1 C648.2 C649.2 C650.1 C651.1 C652.1 C653.1 C654.1 C655.1 C656.1 C657.1 C658.1 C659.1 C660.2 C661.2 C662.1 C663.1 C664.1 C665.1 C671.2 C673.2 C678.2 C679.1 C680.1 C685.1 C686.1 C687.1 C688.1 C689.1 C690.1 C693.2 C694.2 C695.2 C696.1 C698.1 C699.2 C700.1 C701.1 C702.1 C703.1 C704.2 C705.2 C706.2 C707.2 C708.1 C709.1 C710.2 C711.2 C712.2 C713.2 C714.2 C715.2 C716.1 C718.2 C720.2 C722.2 C723.2 C724.2 C725.2 C726.2 C727.2 C728.2 C729.2 C730.2 C731.2 C732.2 C733.2 C734.2 C735.2 C736.2 C737.2 C739.2 C741.2 C742.2 C746.1 C747.1 C758.1 C759.2 C761.1 C768.2 C771.2 C772.2 C773.1 C774.2 C775.1 C776.2 C777.2 C778.2 C781.2 C782.2 C785.1 C786.1 C787.1 C790.1 C791.1 C792.2 C793.1 C794.1 C795.1 C796.1 C797.2 C802.1 C803.2 C804.2 C805.2 C807.1 C808.1 C942.1 C992.2 C2764.1 C2765.1 C2766.2 C2767.2 C2768.1 C2769.1 C2770.1 C2771.1 C2772.1 C2773.1 C2774.1 C2775.1 C2776.1 C2777.1 C2778.2 C2779.1 C2780.1 C2781.2 C2782.2 C2783.1 C2784.2 C2785.1 C2786.2 C2787.2 C2788.1 C2789.2 C2790.2 C2791.2 C2833.2 C2834.1 C2835.2 C2836.2 C2837.1 C2838.1 C2839.2 C2852.2 C2853.2 C2854.2 CN1.1(VSS47) CN1.2(VSS48) CN1.5(VSS46) CN1.6(VSS49) CN1.9(VSS45) CN1.10(VSS50) CN1.14(VSS51) CN1.15(VSS44) CN1.18(VSS52) CN1.19(VSS43) CN1.22(VSS53) CN1.23(VSS42) CN1.26(VSS54) CN1.27(VSS41) CN1.30(VSS55) CN1.31(VSS40) CN1.35(VSS39) CN1.36(VSS56) CN1.39(VSS38) CN1.40(VSS57) CN1.43(VSS37) CN1.44(VSS58) CN1.47(VSS36) CN1.48(VSS59) CN1.51(VSS35) CN1.52(VSS60) CN1.56(VSS61) CN1.57(VSS34) CN1.60(VSS62) CN1.61(VSS33) CN1.64(VSS63) CN1.65(VSS32) CN1.68(VSS64) CN1.69(VSS31) CN1.72(VSS65) CN1.73(VSS30) CN1.77(VSS29) CN1.78(VSS66) CN1.81(VSS28) CN1.82(VSS67) CN1.85(VSS27) CN1.86(VSS68) CN1.89(VSS26) CN1.90(VSS69) CN1.93(VSS25) CN1.94(VSS70) CN1.98(VSS71) CN1.99(VSS24) CN1.102(VSS72) CN1.103(VSS23) CN1.106(VSS73) CN1.107(VSS22) CN1.167(VSS21) CN1.168(VSS74) CN1.171(VSS20) CN1.172(VSS75) CN1.175(VSS19) CN1.176(VSS76) CN1.180(VSS77) CN1.181(VSS18) CN1.184(VSS78) CN1.185(VSS17) CN1.188(VSS79) CN1.189(VSS16) CN1.192(VSS80) CN1.193(VSS15) CN1.196(VSS81) CN1.197(VSS14) CN1.201(VSS13) CN1.202(VSS82) CN1.205(VSS12) CN1.206(VSS83) CN1.209(VSS11) CN1.210(VSS84) CN1.213(VSS10) CN1.214(VSS85) CN1.217(VSS9) CN1.218(VSS86) CN1.222(VSS87) CN1.223(VSS8) CN1.226(VSS88) CN1.227(VSS7) CN1.230(VSS89) CN1.231(VSS6) CN1.234(VSS90) CN1.235(VSS5) CN1.238(VSS91) CN1.239(VSS4) CN1.243(VSS3) CN1.244(VSS92) CN1.247(VSS2) CN1.248(VSS93) CN1.251(VSS1) CN1.252(VSS94) CN1.E1 CN1.E2 CN3.E1 CN3.E2 CN3.P4 CN3.P5 CN3.P6 CN3.P10 CN3.P12 CN3.S1 CN3.S4 CN3.S7 CN5.1(GND_1) CN5.3(GND_3) CN5.9(GND_9) CN5.15(GND_15) CN5.21(GND_21) CN5.27(GND_27) CN5.33(GND_33) CN5.39(GND_39) CN5.45(GND_45) CN5.51(GND_51) CN5.57(GND_57) CN5.71(GND_71) CN5.73(GND_73) CN5.75(GND_75) CN5.E1 CN5.E2 CN7.2(1-) CN9.C CN14.E1 CN14.E2 CN16.3 CN16.16 CN16.17 CN16.19 CN16.E1 CN16.E2 CN21.E1 CN21.E2 CN22.4(GND1) CN22.E1(GND2) CN22.E2(GND3) CN23.4(GND1) CN23.E1(GND2) CN23.E2(GND3) CN24.4(GND1) CN24.7(GND_DRAIN) CN24.E1(GND2) CN24.E2(GND3) CN24.E3(GND4) CN24.E4(GND5) CN25.4 CN25.E1 CN25.E2 CN26.1(GND_1) CN26.7(GND_7) CN26.18(GND_18) CN26.23(GND_23) CN26.24(GND_24) CN26.29(GND_29) CN26.33(GND_33) CN26.36(GND_36) CN26.39(GND_39) CN26.45(GND_45) CN26.51(GND_51) CN26.57(GND_57) CN26.63(GND_63) CN26.69(GND_69) CN26.75(GND_75) CN26.E1 CN26.E2 CN35.1 CN35.4 CN35.7 CN35.12 CN35.19 CN35.20 CN35.21 CN35.22 CN35.25 CN35.28 CN35.31 CN35.34 CN35.37 CN35.40 CN35.E1 CN35.E2 CN36.4(GND1) CN36.7(GND_DRAIN) CN36.E1(GND2) CN36.E2(GND3) CN36.E3(GND4) CN36.E4(GND5) CN37.3(VSS1) CN37.6(VSS2) CN37.E1 CN37.E2 CN37.E3 CN37.E4 CP1.2 CP2.2 CP3.2 CP4.2 CP7.2 CP8.2 CP9.2 CP10.2 CP13.2 CP14.2 CP15.2 CP18.2 CP20.2 CP50.2 CP51.2 CP52.2 D6.P D7.P D8.P D19.P D20.P D21.P D22.P D23.P D28.P D2512.P D2513.P FB6.1 FB14.1 FB17.1 FB18.1 J5.E1 J5.E2 MH1.1 MH4.1 MH6.1 MH7.1 MH8.1 MH9.1 MH10.1 MH22.1 MH26.1 MH27.1 MH28.1 MH29.1 MH30.1 MH31.1 MH32.1 MH33.1 Q1.2(S) Q4.2(S) Q19.2(S) Q20.2(S) Q21.2(S) Q30.4 Q31.4 Q45.2(S) Q46.2(S) Q47.2(GND) Q48.2(S) Q49.2(GND) Q52.2(S) Q53.2(S) Q55.4 Q56.2(S) Q57.2(S) Q61.2(S) Q62.2(S) Q63.2(S) Q64.2(S) Q65.2(S) Q66.2(S) Q67.2(S) Q70.1(S1) Q70.2(S2) Q70.3(S3) Q72.1(S1) Q72.2(S2) Q72.3(S3) Q73.4 Q74.2(S) Q76.2(S) R8.1 R13.2 R17.2 R26.2 R39.1 R40.1 R41.2 R42.2 R43.2 R44.2 R46.2 R47.2 R48.1 R49.1 R50.2 R51.1 R52.1 R53.1 R60.2 R66.1 R74.1 R80.2 R81.1 R91.1 R101.2 R116.2 R117.2 R118.2 R130.2 R196.2 R219.2 R229.1 R232.1 R233.1 R234.1 R235.1 R240.2 R307.1 R308.1 R309.1 R310.1 R312.2 R316.2 R323.2 R341.1 R368.1 R378.2 R390.1 R414.2 R415.2 R421.2 R423.2 R424.1 R426.1 R435.2 R436.2 R440.1 R455.2 R456.2 R463.1 R469.1 R489.2 R513.1 R536.1 R543.2 R547.2 R555.2 R557.1 R560.1 R562.1 R590.1 R636.1 R638.1 R648.2 R669.2 R673.1 R680.1 R682.1 R717.1 R718.1 R720.1 R721.2 R722.1 R723.1 R724.1 R725.1 R726.1 R727.1 R728.1 R729.1 R730.1 R731.1 R754.2 R755.2 R756.1 R762.2 R766.1 R773.1 R778.1 R779.2 R784.2 R785.2 R789.1 R802.1 R812.1 R821.1 R825.2 R830.2 R883.1 R958.1 R2986.1 R2987.1 R2994.1 R3009.2 R3102.1 R3106.2 R3111.2 R3113.2 R3114.1 R3115.1 R3116.1 R3117.1 R3124.2 R3125.2 SW1.2 SW1.E1 SW1.E2 U1.A5(VSS_A5) U1.A67(VSS_A67) U1.A70(VSS_A70) U1.AA2(VSS_AA2) U1.AA4(VSS_AA4) U1.AA65(VSS_AA65) U1.AA68(VSS_AA68) U1.AB8(VSS_AB8) U1.AB15(VSS_AB15) U1.AB16(VSS_AB16) U1.AB18(VSS_AB18) U1.AB21(VSS_AB21) U1.AD8(VSS_AD8) U1.AD13(VSS_AD13) U1.AD16(VSS_AD16) U1.AD19(VSS_AD19) U1.AD20(VSS_AD20) U1.AD21(VSS_AD21) U1.AD62(VSS_AD62) U1.AE64(VSS_AE64) U1.AE65(VSS_AE65) U1.AE66(VSS_AE66) U1.AE67(VSS_AE67) U1.AE68(VSS_AE68) U1.AE69(VSS_AE69) U1.AF1(VSS_AF1) U1.AF2(VSS_AF2) U1.AF4(VSS_AF4) U1.AF10(VSS_AF10) U1.AF15(VSS_AF15) U1.AF17(VSS_AF17) U1.AF63(VSS_AF63) U1.AG16(VSS_AG16) U1.AG17(VSS_AG17) U1.AG18(VSS_AG18) U1.AG19(VSS_AG19) U1.AG20(VSS_AG20) U1.AG21(VSS_AG21) U1.AG71(VSS_AG71) U1.AH6(VSS_AH6) U1.AH13(VSS_AH13) U1.AH63(VSS_AH63) U1.AH64(VSS_AH64) U1.AH67(VSS_AH67) U1.AJ4(VSS_AJ4) U1.AJ15(VSS_AJ15) U1.AJ18(VSS_AJ18) U1.AJ20(VSS_AJ20) U1.AK8(VSS_AK8) U1.AK11(VSS_AK11) U1.AK16(VSS_AK16) U1.AK18(VSS_AK18) U1.AK21(VSS_AK21) U1.AK22(VSS_AK22) U1.AK27(VSS_AK27) U1.AK63(VSS_AK63) U1.AK68(VSS_AK68) U1.AK69(VSS_AK69) U1.AL2(VSS_AL2) U1.AL4(VSS_AL4) U1.AL28(VSS_AL28) U1.AL32(VSS_AL32) U1.AL35(VSS_AL35) U1.AL38(VSS_AL38) U1.AL45(VSS_AL45) U1.AL48(VSS_AL48) U1.AL52(VSS_AL52) U1.AL55(VSS_AL55) U1.AL58(VSS_AL58) U1.AL64(VSS_AL64) U1.AL65(VSS_AL65) U1.AL66(VSS_AL66) U1.AM8(VSS_AM8) U1.AM13(VSS_AM13) U1.AM21(VSS_AM21) U1.AM25(VSS_AM25) U1.AM27(VSS_AM27) U1.AM43(VSS_AM43) U1.AM45(VSS_AM45) U1.AM46(VSS_AM46) U1.AM55(VSS_AM55) U1.AM60(VSS_AM60) U1.AM61(VSS_AM61) U1.AM68(VSS_AM68) U1.AM71(VSS_AM71) U1.AN20(VSS_AN20) U1.AN23(VSS_AN23) U1.AN28(VSS_AN28) U1.AN30(VSS_AN30) U1.AN32(VSS_AN32) U1.AN33(VSS_AN33) U1.AN35(VSS_AN35) U1.AN37(VSS_AN37) U1.AN38(VSS_AN38) U1.AN40(VSS_AN40) U1.AN42(VSS_AN42) U1.AN58(VSS_AN58) U1.AN63(VSS_AN63) U1.AP10(VSS_AP10) U1.AP18(VSS_AP18) U1.AP20(VSS_AP20) U1.AP23(VSS_AP23) U1.AP28(VSS_AP28) U1.AP32(VSS_AP32) U1.AP35(VSS_AP35) U1.AP38(VSS_AP38) U1.AP42(VSS_AP42) U1.AP58(VSS_AP58) U1.AP63(VSS_AP63) U1.AP68(VSS_AP68) U1.AP70(VSS_AP70) U1.AR5(VSS_AR5) U1.AR8(VSS_AR8) U1.AR11(VSS_AR11) U1.AR15(VSS_AR15) U1.AR16(VSS_AR16) U1.AR20(VSS_AR20) U1.AR23(VSS_AR23) U1.AR28(VSS_AR28) U1.AR35(VSS_AR35) U1.AR42(VSS_AR42) U1.AR43(VSS_AR43) U1.AR45(VSS_AR45) U1.AR46(VSS_AR46) U1.AR48(VSS_AR48) U1.AR50(VSS_AR50) U1.AR52(VSS_AR52) U1.AR53(VSS_AR53) U1.AR55(VSS_AR55) U1.AR58(VSS_AR58) U1.AR63(VSS_AR63) U1.AT2(VSS_AT2) U1.AT4(VSS_AT4) U1.AT20(VSS_AT20) U1.AT23(VSS_AT23) U1.AT28(VSS_AT28) U1.AT35(VSS_AT35) U1.AT42(VSS_AT42) U1.AT56(VSS_AT56) U1.AT58(VSS_AT58) U1.AT63(VSS_AT63) U1.AT68(VSS_AT68) U1.AT71(VSS_AT71) U1.AU10(VSS_AU10) U1.AU15(VSS_AU15) U1.AU20(VSS_AU20) U1.AU32(VSS_AU32) U1.AU38(VSS_AU38) U1.AV1(VSS_AV1) U1.AV68(VSS_AV68) U1.AV69(VSS_AV69) U1.AV70(VSS_AV70) U1.AV71(VSS_AV71) U1.AW6(VSS_AW6) U1.AW8(VSS_AW8) U1.AW10(VSS_AW10) U1.AW12(VSS_AW12) U1.AW14(VSS_AW14) U1.AW16(VSS_AW16) U1.AW18(VSS_AW18) U1.AW21(VSS_AW21) U1.AW23(VSS_AW23) U1.AW26(VSS_AW26) U1.AW28(VSS_AW28) U1.AW30(VSS_AW30) U1.AW32(VSS_AW32) U1.AW34(VSS_AW34) U1.AW36(VSS_AW36) U1.AW38(VSS_AW38) U1.AW41(VSS_AW41) U1.AW43(VSS_AW43) U1.AW45(VSS_AW45) U1.AW47(VSS_AW47) U1.AW49(VSS_AW49) U1.AW51(VSS_AW51) U1.AW53(VSS_AW53) U1.AW55(VSS_AW55) U1.AW57(VSS_AW57) U1.AW60(VSS_AW60) U1.AW62(VSS_AW62) U1.AW64(VSS_AW64) U1.AW66(VSS_AW66) U1.AY66(VSS_AY66) U1.B10(VSS_B10) U1.B14(VSS_B14) U1.B18(VSS_B18) U1.B22(VSS_B22) U1.B30(VSS_B30) U1.B34(VSS_B34) U1.B39(VSS_B39) U1.B44(VSS_B44) U1.B48(VSS_B48) U1.B53(VSS_B53) U1.B58(VSS_B58) U1.B62(VSS_B62) U1.B66(VSS_B66) U1.B71(VSS_B71) U1.BA1(VSS_BA1) U1.BA2(VSS_BA2) U1.BA6(VSS_BA6) U1.BA10(VSS_BA10) U1.BA14(VSS_BA14) U1.BA18(VSS_BA18) U1.BA23(VSS_BA23) U1.BA28(VSS_BA28) U1.BA32(VSS_BA32) U1.BA36(VSS_BA36) U1.BA41(VSS_BA41) U1.BA45(VSS_BA45) U1.BA49(VSS_BA49) U1.BA53(VSS_BA53) U1.BA57(VSS_BA57) U1.BA62(VSS_BA62) U1.BA66(VSS_BA66) U1.BA71(VSS_BA71) U1.BB6(VSS_BB6) U1.BB18(VSS_BB18) U1.BB26(VSS_BB26) U1.BB30(VSS_BB30) U1.BB34(VSS_BB34) U1.BB38(VSS_BB38) U1.BB43(VSS_BB43) U1.BB55(VSS_BB55) U1.BB60(VSS_BB60) U1.BB64(VSS_BB64) U1.BB67(VSS_BB67) U1.BB70(VSS_BB70) U1.C1(VSS_C1) U1.C5(VSS_C5) U1.C25(VSS_C25) U1.D6(VSS_D6) U1.D10(VSS_D10) U1.D11(VSS_D11) U1.D14(VSS_D14) U1.D18(VSS_D18) U1.D22(VSS_D22) U1.D25(VSS_D25) U1.D26(VSS_D26) U1.D30(VSS_D30) U1.D34(VSS_D34) U1.D39(VSS_D39) U1.D44(VSS_D44) U1.D45(VSS_D45) U1.D47(VSS_D47) U1.D48(VSS_D48) U1.D53(VSS_D53) U1.D58(VSS_D58) U1.D62(VSS_D62) U1.D66(VSS_D66) U1.D69(VSS_D69) U1.E6(VSS_E6) U1.E11(VSS_E11) U1.E15(VSS_E15) U1.E18(VSS_E18) U1.E21(VSS_E21) U1.E46(VSS_E46) U1.E50(VSS_E50) U1.E53(VSS_E53) U1.E56(VSS_E56) U1.E65(VSS_E65) U1.E71(VSS_E71) U1.F1(VSS_F1) U1.F2(VSS_F2) U1.F4(VSS_F4) U1.F8(VSS_F8) U1.F13(VSS_F13) U1.F22(VSS_F22) U1.F23(VSS_F23) U1.F27(VSS_F27) U1.F28(VSS_F28) U1.F32(VSS_F32) U1.F33(VSS_F33) U1.F35(VSS_F35) U1.F37(VSS_F37) U1.F38(VSS_F38) U1.F40(VSS_F40) U1.F42(VSS_F42) U1.F68(VSS_F68) U1.G5(VSS_G5) U1.G6(VSS_G6) U1.G10(VSS_G10) U1.G22(VSS_G22) U1.G43(VSS_G43) U1.G45(VSS_G45) U1.G48(VSS_G48) U1.G52(VSS_G52) U1.G55(VSS_G55) U1.G58(VSS_G58) U1.G60(VSS_G60) U1.G63(VSS_G63) U1.G66(VSS_G66) U1.H15(VSS_H15) U1.H18(VSS_H18) U1.H71(VSS_H71) U1.J8(VSS_J8) U1.J11(VSS_J11) U1.J13(VSS_J13) U1.J25(VSS_J25) U1.J28(VSS_J28) U1.J32(VSS_J32) U1.J35(VSS_J35) U1.J38(VSS_J38) U1.J42(VSS_J42) U1.K16(VSS_K16) U1.K18(VSS_K18) U1.K22(VSS_K22) U1.K61(VSS_K61) U1.K63(VSS_K63) U1.K64(VSS_K64) U1.K65(VSS_K65) U1.K66(VSS_K66) U1.K67(VSS_K67) U1.K68(VSS_K68) U1.K70(VSS_K70) U1.K71(VSS_K71) U1.L2(VSS_L2) U1.L4(VSS_L4) U1.L8(VSS_L8) U1.L11(VSS_L11) U1.L16(VSS_L16) U1.L17(VSS_L17) U1.L18(VSS_L18) U1.L20(VSS_L20) U1.N6(VSS_N6) U1.N10(VSS_N10) U1.N13(VSS_N13) U1.N19(VSS_N19) U1.N21(VSS_N21) U1.N65(VSS_N65) U1.N68(VSS_N68) U1.P17(VSS_P17) U1.P19(VSS_P19) U1.P20(VSS_P20) U1.P21(VSS_P21) U1.R6(VSS_R6) U1.R13(VSS_R13) U1.T2(VSS_T2) U1.T4(VSS_T4) U1.T15(VSS_T15) U1.T17(VSS_T17) U1.T18(VSS_T18) U1.T21(VSS_T21) U1.U10(VSS_U10) U1.U63(VSS_U63) U1.U64(VSS_U64) U1.U66(VSS_U66) U1.U67(VSS_U67) U1.U69(VSS_U69) U1.U70(VSS_U70) U1.V16(VSS_V16) U1.V17(VSS_V17) U1.V18(VSS_V18) U1.W6(VSS_W6) U1.W9(VSS_W9) U1.W13(VSS_W13) U1.Y17(VSS_Y17) U1.Y19(VSS_Y19) U1.Y20(VSS_Y20) U1.Y21(VSS_Y21) U2.3(GND) U4.3(GND) U5.5(GND) U6.3(GND) U8.2(GND) U9.24(GND) U9.E1(EPAD) U10.3(GND) U12.2(GND) U13.3(GND) U14.3(GND) U16.4(DVSS) U16.E1 U17.3(GND) U18.3(GND) U19.2(GND) U21.1(GND) U22.1(VSS1) U22.27(VSS2) U22.49(VSS3) U22.75(AVSS) U22.91(VSS6) U22.113(VSS5) U22.122(VSS4) U23.3(GND) U24.4(GND) U25.2(GND) U27.3(GND) U29.4(VTTGND) U29.11(PGND1) U29.12(PGND2) U29.13(PGND3) U29.14(PGND4) U29.15(PGND5) U29.16(PGND6) U29.30(VTTGND2) U29.32(GND) U29.34(VTTGND1) U35.1(GND) U38.2(GND) U39.2(GND) U40.2(GND) U41.7(GND) U41.8(PGND) U41.E1 U42.4(GND) U45.4(GND) U45.E1(E_PAD) U50.4(GND) U50.E1(E_PAD) U54.4(GND) U54.E1(E_PAD) U56.5(GND) U56.E1 U59.5(GND) U59.E1 U67.5(GND) U67.E1 U70.E1 U71.E1 U95.E1 U103.E1 U2523.3(GND) U2524.3(GND) U2525.1(A0/E0) U2525.2(A1/E1) U2525.3(A2/E2) U2525.4(GND) U2526.3(GND) U2526.17(GNDX) U2526.18(GNDX_1) U2526.28(GND1) U2526.E1 U2527.1(A0/E0) U2527.2(A1/E1) U2527.3(A2/E2) U2527.4(GND) U2529.3(GND) U2529.E1 X1.2 X1.4 X3.2 X3.4 X4.2 X4.3
GND_EARTH: C399.2 C400.1 C401.1 C402.2 C403.1 C404.1 CN10.E1 CN10.E2 FB6.2 FB17.2 FB18.2
V1.05A_PWRGD: R767.1 U22.34(PWM7/RIG1#/GPA7) U41.6(PGOOD)
V1.5S_PWRGD: R537.2 U22.57(KSO17/SMISO/GPC5(3)) U35.7(POK)
V1.8A_PWRGD: R774.2 U70.4(POK)
V1P0_DRVH: R765.1 U41.13(DRVH)
V1P0_DRVL: R768.1 U41.9(DRVL)
V1P0_LL: C344.1 L12.1 Q55.5 Q55.6 Q55.7 R392.2 U41.12(LL)
VBAT: R381.2 R390.2 U22.3(VBAT)
VCC1_USB3.0: C407.2 C408.2 C409.1 CN36.1(VBUS) F2.2 R339.2 U12.1(VOUT)
VCC2_USB3.0: C707.1 C715.1 C726.1 CN24.1(VBUS) CP20.1 F3.2 R559.2 U38.1(VOUT)
VCC_8625: C2766.1 FB39.1 FB45.1 R2988.2 R2991.1 R2992.1 R2998.2 R2999.2 U2525.8(VCC) U2526.13(VDDIOX) U2526.14(VDDIOX_1) U2527.8(VCC)
VCC_USB2: C712.1 C729.1 C739.1 CN22.1(VBUS) F4.2 R569.2 U39.1(VOUT)
VCC_USB3: C660.1 C741.1 C742.1 CN23.1(VBUS) F5.2 R570.2 U40.1(VOUT)
VCCCORE_SENSE: R683.2 U1.E32(VCCCORE_SENSE)
VCCCORE_SENSE_IC: R222.2 R226.2 R227.2 U103.17(FB_A)
VCCGT_SENSE: R667.1 U1.J70(VCCGT_SENSE)
VCCRTCEXT: C13.2 U1.BB10(VCCRTCEXT_BB10)
VCCSA_IMON: C319.1 R233.2 U103.23(IMON_C)
VCCSA_SENSE: R674.1 U1.H20(VCCSA_SENSE)
VCCSA_SENSE_IC: R185.2 R230.2 R231.2 U103.25(FB_C)
VCCST_PWRGD: Q1.3(D) R20.2 R22.2
VCCST_PWRGD_MCP: R22.1 U1.B65(VCCST_PWRGD)
VCCSTG_EN: R660.2 U67.3(ON)
VCCSTG_EN_R: R660.1 U6.4(Y)
VDD12: C2767.1 C2768.2 C2771.2 FB38.2 L9.1 U2526.19(VDD12)
VDD18: C2785.2 U95.18(VDD18)
VDDIO_8625: C2764.2 C2765.2 FB37.2 FB44.2 R2989.2 R2990.2 R2993.2 R2995.2 R2996.2 U2526.38(VDDIO) U2526.50(VDDIO_1)
VDDRX: C2772.2 C2773.2 C2774.2 FB38.1 U2526.6(VDDRX)
VIN_LCD: C603.1 C607.2 C2835.1 F9.1 L32.1 R3089.2 R3090.2 U2529.13(VIN)
VSSCORE_SENSE: R684.2 U1.E33(VSSCORE_SENSE)
VSSCORE_SENSE_IC: C317.2 R682.2 R684.1 U103.18(RTN_A)
VSSGT_SENSE: R668.1 U1.J69(VSSGT_SENSE)
VSSSA_SENSE: R675.1 U1.H21(VSSSA_SENSE)
VSSSA_SENSE_IC: C320.2 R673.2 R675.2 U103.26(RTN_C)
8625_PD#: C2770.2 R2990.1 U2526.10(PD#)
8625_PWMO: R528.2 U2526.12(PWMO)
8625_RST#: C2769.2 R2989.1 U2526.9(RST#)
+V_ADP_IN: C368.2 C369.2 C784.2 C787.2 FB4.1 FB5.1 Q58.1(S1) Q58.2(S2) Q58.3(S3) R303.2 R788.2 R791.2 R793.1
+V_LED: C298.1 C2791.1 C2833.1 CN41.1 CP50.1 D38.N D42.N J5.3 J5.4 R645.1 R3096.1
+VSYS_DCIN: C293.1 C329.1 C535.1 C633.1 C634.1 C635.1 C648.1 C649.1 C671.1 C673.1 C693.1 C694.1 C695.1 C775.2 C782.1 C786.2 C805.1 F9.2 FB22.2 FB23.2 FB24.2 FB25.2 FB26.1 Q30.1 Q30.2 Q31.1 Q31.2 Q55.1 Q55.2 Q58.5(D1) Q58.6(D2) Q58.7(D3) Q58.8(D4) R793.2 R794.2 U29.21(VIN1) U29.22(VIN2) U29.23(VIN3) U29.24(VIN4) U29.33(VIN) U71.12(VIN) U103.33(VIN)
A_POWER_OK: R17.1 R409.2 U1.BB20(DSW_PWROK)
AC_PRESENT: R10.2 U1.AY15(GPD_1_ACPRESENT) U22.120(TMRI0/WUI2/GPC4(3))
AC_VREF: C428.1 C432.2 U16.28(VREF)
ADP_IN#: R405.2 U22.71(ADC5/DCD1#/WUI29/GPI5(3))
ALL_SYS_PWRGD_VRON: R402.1 U103.40(VR_ENABLE)
AUD_MIC1_IN_L: R348.2 R355.1 R3121.2
AUD_MIC1_IN_R: R347.2 R356.1 R3120.2
AUD_MIC_IN_L: C2845.2 U16.17(MIC2-L(PORT-F-L))
AUD_MIC_IN_R: C2844.2 U16.18(MIC2-R(PORT-F-R))
AUDIO_DVDD_IO: C454.2 R360.1 R361.1 R831.1 U16.9(DVDD-IO)
AUXN_LVDS: C2848.1 U2526.1(DAUXN)
AUXP_LVDS: C2849.1 U2526.2(DAUXP)
BAT-DEK#: R406.1 R419.2
BKUP_BAT: CN7.1(1+) R182.2
BL_ADJ: R2985.1 R3109.1 U22.30(PWM4/GPA4)
BLCTL: R415.1 R454.2 R466.2 U27.1(A)
BT_ON: R196.1 R457.2 R3007.2
BT_RF_KILL_R*: CN26.54(W_DISABLE2* (O)(0/3.3V)) R3007.1
CA_VREF_CHB: C250.2 C416.2 CN1.164(VREFCA) R45.1 R368.2 R476.2
CFG<0>: R717.2 U1.E68(NOA_N_0)
CFG<1>: R722.2 U1.B67(NOA_N_1)
CFG<2>: R723.2 U1.D65(NOA_N_2)
CFG<3>: R724.2 U1.D67(NOA_N_3)
CFG<4>: R721.1 U1.E70(NOA_N_4)
CFG<5>: R727.2 U1.C68(NOA_N_5)
CFG<6>: R726.2 U1.D68(NOA_N_6)
CFG<8>: R725.2 U1.F71(NOA_N_8)
CFG<9>: R728.2 U1.G69(NOA_N_9)
CFG<10>: R729.2 U1.F70(NOA_N_10)
CFG<12>: R730.2 U1.H70(NOA_N_12)
CFG<13>: R731.2 U1.G71(NOA_N_13)
CHAGER_IOUT: R218.1 R236.2
CORE_BOO: R239.2 U45.2(BOOT)
CORE_CSP: C299.1 C307.2 R213.2 R214.1 R242.1 U103.19(ISUMP_A)
CORE_FCCM: U45.7(FCCM) U103.21(FCCM_A)
CORE_HG_DRV: R689.1 U45.1(UGATE)
CORE_LG_DRV: R690.1 U45.5(LGATE)
CORE_PHASE: C721.2 LPM1.1 Q69.1(S1) Q69.2(S2) Q69.3(S3) Q70.5(D1) Q70.6(D2) Q70.7(D3) Q70.8(D4) R242.2 U45.8(PHASE)
CORE_PWM1: U45.3(PWM) U103.22(PWM_A)
CPU_POPIRCOMP: R41.1 U1.AT16(CPU_POPIRCOMP)
CPU_SVIDALRT*: R122.1 R125.2 U103.36(ALERT#)
CPU_SVIDCLK: R714.2 R715.2 U1.A63(VIDSCK)
CPU_SVIDDAT: R124.2 R686.1 R713.1 U1.D64(VIDSOUT)
CSI2_COMP: R80.1 U1.E13(CSI2_COMP)
DDR1_B_ALERT_N: CN1.116(ALERT*) R50.1 U1.AN43(DDR1_ALERT_N)
DDR1_B_PARITY: CN1.143(PARITY) U1.AP43(DDR1_PARITY)
DDR3VR_PWRGD: R545.2 U22.25(PWM1/GPA1)
DDR4_DRAMRST#: R502.1 U1.AT13(DRAM_RESETB)
DDR4_DRAMRST_R#: C417.2 CN1.108(RESET*) R498.1 R502.2
DDR_CA_VREF: C7.2 R46.1 U1.AY67(DDR_VREF_CA)
DDR_PG_CTRL: U1.AW67(DDR_VTT_CNTL) U4.2(A)
DDR_STBY: R470.2 R549.1 R550.1 R551.1 U29.5(S3)
DDR_VREFDQ_CHA: C8.2 R47.1 U1.AY68(DDR_VREF_DQ_0)
DDR_VTT_PG_CTRL: R152.2 R548.2 R549.2 U4.4(Y)
DEVICE_PROCHOT*: C487.1 R27.2 R36.1 R685.2 TP17.1 U23.4(Y)
DMIC_CLK: U16.3(GPIO1/DMIC-CLK)
DMIC_DATA: U16.2(GPIO0/DMIC-DATA)
DRVH1: Q30.8 R787.1
DRVH2: Q31.8 R783.2
DRVL1: Q30.3 R786.1
DRVL2: Q31.3 R781.2
EARPHONE_CTRL: J3.6 R102.2 R358.1
EC_HID_INT*: TP13.1 U1.AU11(GPP_A_11_PMEB)
EC_LPC_CLK: U1.AW9(GPP_A_9_CLKOUT_LPC_0_ESPI_CLK) U22.13(LPCCLK/GPM4(3))
EC_MUTE#: R369.2 U17.1(A) U22.28(PWM2/GPA2)
EC_PCH_RCIN*: R92.2 R487.2 U1.AW13(GPP_A_0_RCINB)
EDID_SCL: R2998.1 U2526.29(DDC_SCL) U2527.6(SCL)
EDID_SDA: R2999.1 U2526.30(DDC_SDA) U2527.5(SDA)
EDP_AUX_DN*: C2848.2 U1.E45(EDP_AUXN)
EDP_AUX_DP: C2849.2 U1.F45(EDP_AUXP)
EDP_BKLCTL_3P3: Q48.3(D) R2997.1 R3107.2 R3110.2 R3123.1
EDP_BKLEN_OUT: R452.1 R453.1 R456.1 R541.2 R3094.1
EDP_COMP: R59.1 U1.E52(DP_COMP)
EDP_DISP_UTIL: TP25.1 U1.B52(EDP_DISP_UTIL)
EDP_HPD: R60.1 U1.L10(GPP_E_17_EDP_HPD) U2526.11(HPD)
EDP_TX_DN*<0>: C281.1 U1.C47(EDP_TXN_0)
EDP_TX_DN*<1>: C2846.1 U1.D46(EDP_TXN_1)
EDP_TX_DP<0>: C2850.1 U1.C46(EDP_TXP_0)
EDP_TX_DP<1>: C2847.2 U1.C45(EDP_TXP_1)
EDRAM_EDM: R720.2 U1.AY71(EDRAM_EDM)
EDRAM_OPIO_RCOMP: R43.1 U1.H66(EDRAM_OPIO_RCOMP)
EECS: R310.2 U9.30(EECS)
EEDI: R308.2 U9.32(EEDI)
EMC_THERM#: R524.1 U5.4(T\H\E\R\M\)
EMMC_RCOMP: R81.2 U1.AT1(EMMC_RCOMP)
ENA: R3094.2 U2529.9(ENA)
ENBLT: R541.1 U2526.23(ENBLT)
ENPVCC/I2C_ADDR: R2995.1 U2526.33(ENPVCC/I2C_ADDR)
ENSWREG: R311.2 R312.1 U9.33(ENSWREG)
EOPIO_RCOMP: R44.1 U1.H65(CPU_EOPIO_RCOMP)
EVDD10: C385.2 C386.1 C387.1 C388.1 C389.1 C390.1 C391.1 C392.1 C393.1 C396.2 C397.1 L3.2 U9.3(AVDD10) U9.6(AVDD10(NC)) U9.9(AVDD10A(NC)) U9.13(DVDD10) U9.21(EVDD10) U9.29(DVDD10A) U9.41(DVDD10(NC)) U9.45(AVDD10A)
EXT_BOOT_STALL_STRAP: R733.1 U1.AM7(GPP_B_23_SML1ALERTB_PCHHOTB)
FAN_BACK: CN25.2 D18.P R608.2 R609.2
FAN_PWMIN: CN25.3 R414.1 U22.24(PWM0/GPA0)
FAN_VCC: C609.2 CN25.1 FB21.1
FLASH_SPI_CLK: R137.1 U1.AV2(SPI0_CLK)
FLASH_SPI_CS*: R708.2 U1.AU3(SPI0_FLASH_0_CSB) U42.1(CS*)
FLASH_SPI_D<2>: R87.1 R136.1 U1.AW2(SPI0_IO_2)
FLASH_SPI_D<3>: R86.2 R711.1 U1.AU4(SPI0_IO_3)
FLASH_SPI_MISO: R138.1 U1.AW3(SPI0_MISO_IO_1)
FLASH_SPI_MOSI: R139.1 U1.AV3(SPI0_MOSI_IO_0)
FMISO: U22.103(FMISO/GPG5) U24.2(SO/SIO1)
FMOSI: U22.102(FMOSI/GPG4) U24.5(SI/SIO0)
FSCE#: U22.101(FSCE#/GPG3) U24.1(CS#)
FSCK: U22.105(FSCK/GPG7) U24.6(SCLK)
GA20: R402.2 U22.126(GA20/GPB5(3))
GL834L_3V3: C2782.1 C2783.2 C2784.1 C2787.1 C2790.1 FB19.1 FB20.2 R3008.1 U95.1(DVDD) U95.19(DVDD33_1) U95.23(DVDD33)
GPO: R328.2 U9.38(GPO/SMBALERT)
GPP_B_CORE_VID0: TP2.1 U1.AN11(GPP_B_0_CORE_VID_0_AN11)
GPP_B_CORE_VID1: TP7.1 U1.AN13(GPP_B_1_CORE_VID_1_AN13)
GPP_C_5_SML0ALERTB: R732.1 U1.W1(GPP_C_5_SML0ALERTB)
GPP_G_1: R632.2 U1.AB13(GPP_G_1_SD_DATA0)
GT_BOOT: R249.1 U50.2(BOOT)
GT_CSP: C297.2 R168.1 R184.1 R204.1 R205.2 U103.7(ISUMP_B)
GT_FCCM: U50.7(FCCM) U103.11(FCCM_B)
GT_HG_DRV: R254.1 U50.1(UGATE)
GT_LG_DRV: R256.1 U50.5(LGATE)
GT_PHASE: C738.1 LPM8.2 Q71.1(S1) Q71.2(S2) Q71.3(S3) Q72.5(D1) Q72.6(D2) Q72.7(D3) Q72.8(D4) R184.2 U50.8(PHASE)
GT_PWM: U50.3(PWM) U103.12(PWM1_B)
H_PECI_EC: U1.A54(PECI) U22.117(PECI/SMCLK2/WUI22/GPF6(3))
HDA_BITCLK: C455.2 R621.1 U16.6(BCLK)
HDA_RST#: R372.1 R373.2 R623.1 U16.11(RESETB)
HDA_SDATAIN0: C457.2 R362.2 U1.BA21(AZA_SDI_0_SSP0_RXD)
HDA_SDATAOUT: C458.2 R626.1 U16.5(SDATA-OUT)
HDA_SDOUT: Q51.3(D) Q59.2(S) R624.1 U1.BB22(AZA_SDO_SSP0_TXD)
HDA_SYNC: C456.2 R620.1 U16.10(SYNC)
HP_OUT_L: C421.1 R350.1 R363.1 R365.2
HP_OUT_R: C422.1 R349.1 R364.1 R366.2
HSON: C394.2 U9.23(HSON)
HSOP: C395.2 U9.22(HSOP)
I2C_CLK1: R384.2 R396.2 R434.1 U22.115(SMCLK1/GPC1)
I2C_CLK2_LVDS: R2991.2 U2525.6(SCL) U2526.25(CSCL/MSCL)
I2C_CLK2_THEM: R434.2 U5.8(SMCLK)
I2C_CLK3: R379.2 U22.94(CRX1/WUI17/SIN1/SMCLK3/GPH1/ID1)
I2C_DATA1: R387.2 R397.2 R437.1 U22.116(SMDAT1/GPC2)
I2C_DATA2_LVDS: R2992.2 U2525.5(SDA) U2526.24(CSDA/MSDA)
I2C_DATA2_THEM: R437.2 U5.7(SMDATA)
I2C_DATA3: R380.2 U22.95(CTX1/WUI18/SOUT1/GPH2/SMDAT3/ID)
IINA: CN41.2 R3130.1 R3131.1 R3132.1 R3133.1
IINA0: J5.1 R345.1 R3130.2 U2529.1(ISEN  1)
IINA1: J5.2 R345.2 R3131.2 U2529.2(ISEN 2)
IINA2: R3089.1 R3095.1 R3118.2 R3132.2 U2529.4(ISEN  3)
IINA3: R3090.1 R3095.2 R3097.2 R3133.2 U2529.5(ISEN 4)
IMVP8_PROCHOT*: R685.1 U103.38(VR_HOT#)
IMVP_SVID_CLK: R715.1 U103.37(SCLK)
IMVP_SVID_DATA: R686.2 U103.35(SDA)
INNER_MIC: B1.1(D) C2844.1 C2845.1 CN42.2 R3119.2
INT_SERIRQ: CN16.12 R93.1 U1.AY11(GPP_A_6_SERIRQ) U22.5(SERIRQ/GPM6(3))
ISETA: R638.2 R648.1 R754.1 R3098.2 R3099.2 R3100.2 R3101.2 U2529.6(ISET)
ISH_ALS_INT*: R114.2 U1.BA8(GPP_A_19_ISH_GP_1)
ISH_GYRO1_IRQ*: R115.2 U1.AY8(GPP_A_18_ISH_GP_0)
